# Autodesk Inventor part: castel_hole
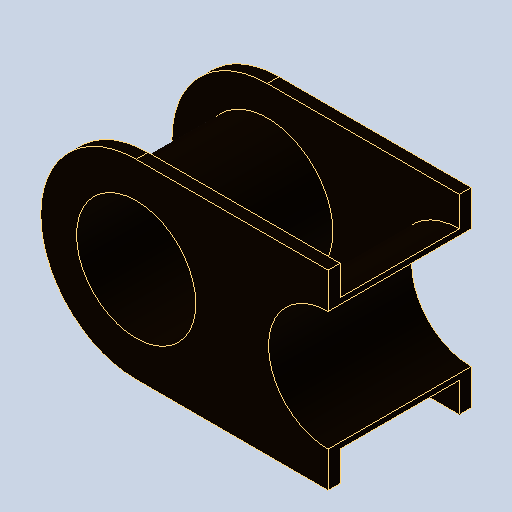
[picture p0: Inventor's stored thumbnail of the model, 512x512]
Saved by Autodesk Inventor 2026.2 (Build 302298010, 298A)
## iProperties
Created: 2026-10
Part Number: castel_hole
Material: Générique
Document SubType Name: Modeling
Designer: mel
Density: 1 g/cm^3
Appearance: Par défaut
Author: mel
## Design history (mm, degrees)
feature "Base1"
node "Solide1"
